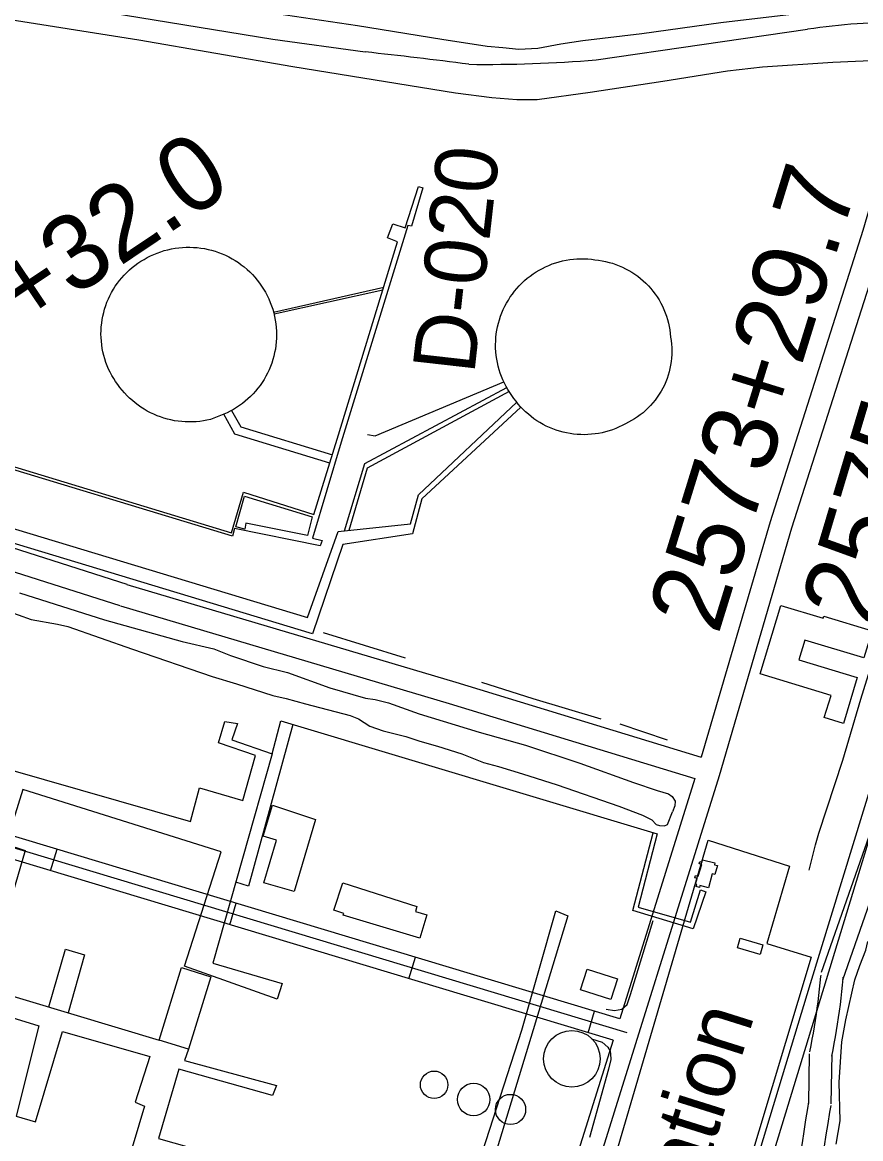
# Model space of a CAD drawing. Extents: x 3535183 to 3573198, y 534952 to 560562.
# Drawn here: x 3562347 to 3563467, y 541660 to 543150 of the extents above; entities that cross this region are included whole.
import ezdxf

# ---------------------------------------------------------------- set-up
doc = ezdxf.new("R2010")
doc.units = 0
for name, color, linetype in [('V-BLDG-OTLN', 7, 'Continuous'), ('V-DOMW-TANK', 7, 'Continuous'), ('V-LEVE-TOET', 7, 'Continuous'), ('V-RIVR-RANG-IDEN', 7, 'Continuous'), ('V-ROAD-CNTR', 7, 'Continuous'), ('V-SITE-OTLN', 7, 'Continuous'), ('V-SITE-OTLN-IDEN', 7, 'Continuous'), ('V-SURV-IDEN', 7, 'Continuous'), ('V-TOPO-SHOR', 7, 'Continuous'), ('V-UTIL-LINE', 7, 'Continuous')]:
    doc.layers.add(name, color=color, linetype=linetype)

msp = doc.modelspace()

# ---------------------------------------------------------------- linework, layer by layer
at = {"layer": 'V-BLDG-OTLN'}
for points in [[(3563427.4, 542251.8), (3563332.5, 542280.5), (3563360.1, 542371.9), (3563416.9, 542354.7), (3563417.8, 542357.6), (3563482.1, 542338.1), (3563471.2, 542301.7), (3563392.4, 542325.5), (3563384.4, 542299.3), (3563462.4, 542275.7), (3563443.9, 542214.4), (3563418.3, 542222.1)], [(3562738.4, 542086), (3562710, 541989.7), (3562669.6, 542001.6), (3562686.4, 542058.6), (3562668.7, 542063.8), (3562680.9, 542105.2)], [(3563255.4, 542032.1), (3563272.1, 542028.2), (3563271.5, 542025.7), (3563275.4, 542024.6), (3563272, 542012.7), (3563268.4, 542013.7), (3563263.7, 541995), (3563252.2, 541997.9), (3563251.6, 541995.1), (3563247.1, 541996.5), (3563247.8, 541999.3), (3563246.3, 541999.7), (3563248.4, 542007.1), (3563245.2, 542008), (3563246.4, 542011.2), (3563249.6, 542010.3), (3563254.5, 542026.1), (3563251.2, 542027), (3563252.1, 542030), (3563255.1, 542029.3)], [(3562887.3, 541958.8), (3562877.8, 541927.7), (3562775.5, 541958.3), (3562776.2, 541960.4), (3562763.1, 541964.8), (3562774.8, 542001.4), (3562874.1, 541969.7), (3562872.1, 541963.3)], [(3563305.9, 541927.6), (3563336.3, 541918.6), (3563332.4, 541905.6), (3563302.2, 541914.6)], [(3562598.8, 541876.1), (3562568.8, 541779.5), (3562529.6, 541791.6), (3562559.6, 541888.4)], [(3563101.6, 541886.3), (3563141.9, 541873.1), (3563133.2, 541845.8), (3563092.7, 541858.7)]]:
    msp.add_lwpolyline(points, close=True, dxfattribs=at)
at = {"layer": 'V-DOMW-TANK'}
for points in [[(3562458.5, 542696.4), (3562457, 542701), (3562455.7, 542705.6), (3562454.5, 542710.3), (3562453.6, 542715.1), (3562452.9, 542719.8), (3562452.4, 542724.6), (3562452, 542729.4), (3562451.9, 542734.2), (3562452, 542739.1), (3562452.3, 542743.9), (3562452.8, 542748.7), (3562453.5, 542753.4), (3562454.4, 542758.2), (3562455.5, 542762.9), (3562456.7, 542767.5), (3562458.2, 542772.1), (3562459.9, 542776.6), (3562461.8, 542781.1), (3562463.8, 542785.4), (3562466, 542789.7), (3562468.5, 542793.9), (3562471, 542797.9), (3562473.8, 542801.9), (3562476.7, 542805.7), (3562479.8, 542809.4), (3562483, 542813), (3562486.4, 542816.5), (3562489.9, 542819.8), (3562493.6, 542822.9), (3562497.3, 542825.9), (3562501.2, 542828.7), (3562505.3, 542831.4), (3562509.4, 542833.8), (3562513.6, 542836.2), (3562518, 542838.4), (3562522.5, 542840.4), (3562527.1, 542842.3), (3562531.7, 542844), (3562536.4, 542845.5), (3562541.2, 542846.7), (3562546, 542847.8), (3562550.8, 542848.7), (3562555.7, 542849.3), (3562560.6, 542849.8), (3562565.6, 542850.1), (3562570.5, 542850.1), (3562575.4, 542849.9), (3562580.4, 542849.6)], [(3562580.4, 542849.6), (3562585.2, 542849), (3562590.1, 542848.2), (3562595, 542847.2), (3562599.7, 542846), (3562604.5, 542844.7), (3562609.1, 542843.1), (3562613.7, 542841.3), (3562618.3, 542839.3), (3562622.7, 542837.2), (3562627, 542834.8), (3562631.3, 542832.3), (3562635.4, 542829.6), (3562639.4, 542826.7), (3562643.3, 542823.7), (3562647.1, 542820.5), (3562650.7, 542817.2), (3562654.2, 542813.7), (3562657.5, 542810), (3562660.7, 542806.2), (3562663.7, 542802.3), (3562666.5, 542798.3), (3562669.2, 542794.1), (3562671.7, 542789.9), (3562674, 542785.5), (3562676.1, 542781.1), (3562678, 542776.5), (3562679.8, 542771.9), (3562681.3, 542767.3), (3562682.7, 542762.5), (3562683.8, 542757.7), (3562684.8, 542752.9), (3562685.5, 542748), (3562686.1, 542743.1), (3562686.4, 542738.2), (3562686.5, 542733.3), (3562686.4, 542728.5), (3562686.1, 542723.7), (3562685.6, 542718.9), (3562684.9, 542714.1), (3562683.9, 542709.4), (3562682.8, 542704.7), (3562681.5, 542700), (3562680, 542695.4), (3562678.4, 542690.9), (3562676.5, 542686.5), (3562674.4, 542682.1), (3562672.2, 542677.8), (3562669.8, 542673.6), (3562667.2, 542669.6), (3562664.4, 542665.6), (3562661.5, 542661.7), (3562658.4, 542658), (3562655.2, 542654.4), (3562651.8, 542651), (3562648.3, 542647.7), (3562644.7, 542644.5), (3562640.9, 542641.5), (3562637, 542638.6), (3562633, 542636), (3562628.9, 542633.4), (3562624.6, 542631.1), (3562620.3, 542628.9), (3562615.9, 542627), (3562598.2, 542620.1), (3562593.4, 542619.1), (3562588.7, 542618.2), (3562583.9, 542617.6), (3562579, 542617.1), (3562574.2, 542616.8), (3562569.3, 542616.8), (3562564.5, 542616.9), (3562559.7, 542617.3), (3562554.8, 542617.8), (3562550, 542618.5), (3562545.3, 542619.5), (3562540.6, 542620.6), (3562535.9, 542622), (3562531.3, 542623.5), (3562526.8, 542625.2), (3562522.3, 542627.1), (3562517.9, 542629.2), (3562513.6, 542631.4), (3562509.4, 542633.9), (3562505.3, 542636.5), (3562501.4, 542639.2), (3562497.5, 542642.2), (3562493.8, 542645.3), (3562490.2, 542648.5), (3562486.7, 542651.9), (3562483.4, 542655.5), (3562480.2, 542659.1), (3562477.2, 542662.9), (3562474.3, 542666.7), (3562471.5, 542670.7), (3562468.9, 542674.7), (3562466.4, 542678.9), (3562464.2, 542683.1), (3562462.1, 542687.5), (3562460.2, 542691.9), (3562458.5, 542696.4)], [(3562998, 542656.1), (3562995.4, 542660.2), (3562993.1, 542664.3), (3562990.8, 542668.6), (3562988.8, 542673), (3562987, 542677.5), (3562985.3, 542682), (3562983.9, 542686.6), (3562982.6, 542691.3), (3562981.5, 542696), (3562980.6, 542700.7), (3562980, 542705.5), (3562979.5, 542710.3), (3562979.2, 542715.2), (3562979.1, 542720), (3562979.3, 542724.8), (3562979.6, 542729.6), (3562980.1, 542734.4), (3562980.9, 542739.2), (3562981.8, 542743.9), (3562982.9, 542748.6), (3562984.3, 542753.3), (3562985.8, 542757.9), (3562987.5, 542762.4), (3562989.4, 542766.8), (3562991.5, 542771.2), (3562993.7, 542775.5), (3562996.2, 542779.6), (3562998.8, 542783.7), (3563001.5, 542787.6), (3563004.5, 542791.5), (3563007.6, 542795.2), (3563010.8, 542798.7), (3563014.2, 542802.2), (3563017.8, 542805.5), (3563021.4, 542808.6), (3563025.2, 542811.6), (3563029.2, 542814.4), (3563033.2, 542817.1), (3563037.3, 542819.5), (3563041.6, 542821.8), (3563045.9, 542824), (3563050.3, 542825.9), (3563054.8, 542827.7), (3563059.4, 542829.2), (3563064, 542830.6), (3563068.7, 542831.8), (3563073.5, 542832.8), (3563078.2, 542833.5), (3563083, 542834.1), (3563087.8, 542834.5), (3563092.7, 542834.7), (3563097.5, 542834.7), (3563102.3, 542834.4), (3563107.1, 542834), (3563111.9, 542833.4)], [(3563111.9, 542833.4), (3563116.7, 542832.6), (3563121.4, 542831.9), (3563126.1, 542831), (3563130.7, 542829.9), (3563135.3, 542828.6), (3563139.8, 542827.1), (3563144.2, 542825.4), (3563148.6, 542823.5), (3563152.9, 542821.4), (3563157.1, 542819.2), (3563161.2, 542816.7), (3563165.2, 542814.1), (3563169.1, 542811.3), (3563172.8, 542808.4), (3563176.4, 542805.3), (3563179.9, 542802.1), (3563183.2, 542798.7), (3563186.4, 542795.1), (3563189.4, 542791.4), (3563192.3, 542787.6), (3563195, 542783.7), (3563197.5, 542779.7), (3563199.9, 542775.5), (3563202.1, 542771.3), (3563204.1, 542767), (3563205.9, 542762.6), (3563207.5, 542758.1), (3563208.9, 542753.5), (3563210.1, 542748.9), (3563211.1, 542744.3), (3563211.9, 542739.6), (3563212.5, 542734.9), (3563212.9, 542730.1), (3563213.7, 542725.5), (3563214.2, 542720.8), (3563214.5, 542716.1), (3563214.6, 542711.5), (3563214.6, 542706.8), (3563214.3, 542702.1), (3563213.7, 542697.4), (3563213, 542692.8), (3563212.1, 542688.2), (3563211, 542683.6), (3563209.7, 542679.1), (3563208.2, 542674.7), (3563206.5, 542670.3), (3563204.6, 542666), (3563202.5, 542661.8), (3563200.2, 542657.7), (3563197.8, 542653.7), (3563195.2, 542649.8), (3563192.4, 542646), (3563189.4, 542642.4), (3563186.3, 542638.9), (3563183, 542635.5), (3563179.6, 542632.3), (3563176.1, 542629.2), (3563172.4, 542626.3), (3563168.6, 542623.6), (3563164.7, 542621), (3563160.7, 542618.6), (3563156.5, 542616.4), (3563152.6, 542614.5), (3563148.4, 542612.2), (3563144.1, 542610.1), (3563139.7, 542608.2), (3563135.2, 542606.5), (3563130.7, 542605), (3563126.1, 542603.7), (3563121.4, 542602.5), (3563116.7, 542601.6), (3563112, 542600.9), (3563107.3, 542600.3), (3563102.5, 542600), (3563097.7, 542599.8), (3563092.9, 542599.9), (3563088.1, 542600.2), (3563083.4, 542600.6), (3563078.7, 542601.3), (3563073.9, 542602.1), (3563069.3, 542603.2), (3563064.7, 542604.4), (3563060.1, 542605.9), (3563055.6, 542607.5), (3563051.2, 542609.3), (3563046.8, 542611.4), (3563042.6, 542613.5), (3563038.4, 542615.9), (3563034.4, 542618.4), (3563030.4, 542621.1), (3563026.6, 542624), (3563022.9, 542627), (3563019.3, 542630.2), (3563015.9, 542633.5), (3563012.6, 542637), (3563009.5, 542640.6), (3563006.5, 542644.4), (3563003.6, 542648.2), (3563000.7, 542652.1), (3562998, 542656.1)]]:
    msp.add_lwpolyline(points, dxfattribs=at)
for centre, radius in [((3563081.1, 541766.6), 37.8), ((3562897, 541731.8), 18.4), ((3562949.8, 541712.2), 21.7), ((3562999.1, 541698.9), 20.2)]:
    msp.add_circle(centre, radius, dxfattribs=at)
at = {"layer": 'V-LEVE-TOET'}
msp.add_lwpolyline([(3563374.4, 543161), (3563280.1, 543149.6), (3563174.7, 543134.9), (3563095.8, 543125.7), (3563066.2, 543121), (3563035.4, 543115.5), (3563010.2, 543114.2), (3562989, 543116.1), (3562967.7, 543117.9), (3562907.2, 543127.4), (3562794.4, 543145.5), (3562674.5, 543163.6)], dxfattribs=at)
at = {"layer": 'V-ROAD-CNTR'}
for p, q in [((3562384.6, 542017.6), (3562393.2, 542046.3)), ((3562624, 541945.5), (3562632.6, 541974.3)), ((3562863.4, 541873.5), (3562872, 541902.2)), ((3563102.7, 541801.4), (3563111.4, 541830.1))]:
    msp.add_line(p, q, dxfattribs=at)
for points in [[(3562364.2, 543179.5), (3562681.6, 543128), (3562804.9, 543110.8)], [(3563551, 543149), (3563469.9, 542872.3), (3563345.8, 542483.6), (3563253.9, 542169.3)], [(3563580.9, 543140.1), (3563498.6, 542863.5), (3563374.5, 542474.8), (3563277.9, 542144.5), (3563109.1, 541604.2), (3563005.5, 541244.6)], [(3563113.6, 543100.4), (3563395.8, 543141.1)], [(3562486.8, 542399.8), (3562266.4, 542469.9), (3561935.4, 542567.8), (3561653.6, 542653.5), (3561243.7, 542788.4), (3561211.6, 542762.2), (3561208.6, 542724.7), (3561209.1, 542681.9), (3561219, 542659.5)], [(3563414.6, 541882), (3563493.9, 542108.1), (3563535.3, 542266.7), (3563581.7, 542416.5), (3563614.7, 542534.6)], [(3562477.7, 542371.2), (3562257.6, 542441.2), (3562153.2, 542472.1)], [(3562486.6, 542399.9), (3562925.8, 542269.6), (3563253.9, 542169.3)], [(3562478, 542371.1), (3562917.2, 542240.8), (3563245.2, 542140.6)], [(3563245.2, 542140.6), (3563145.1, 541820)], [(3563145.1, 541820), (3562118.9, 542128.9)], [(3563154.9, 541801.3), (3562114.6, 542114.6)], [(3563136.1, 541791.3), (3562110.3, 542100.2)], [(3563443, 541872), (3563515.7, 542079.6)], [(3563398.9, 541775.9), (3563400.6, 541784.3), (3563402.2, 541792.6), (3563403.7, 541800.9), (3563405.1, 541809.3), (3563406.5, 541817.6), (3563407.7, 541826), (3563408.9, 541834.3), (3563410, 541842.7), (3563411.1, 541851.1), (3563412, 541859.5), (3563412.9, 541867.9), (3563413.7, 541876.3), (3563413.9, 541878.3)], [(3563428.4, 541770.1), (3563430.1, 541778.6), (3563431.7, 541787.1), (3563433.2, 541795.7), (3563434.7, 541804.3), (3563436.1, 541813), (3563437.4, 541821.6), (3563438.6, 541830.2), (3563439.8, 541838.9), (3563440.8, 541847.6), (3563441.8, 541856.2), (3563442.7, 541864.9), (3563443.6, 541873.6), (3563443.7, 541875.7)], [(3563136.1, 541791.3), (3563080.3, 541612.9), (3562976.8, 541253.5)], [(3563397.5, 541707), (3563398.7, 541773.3)], [(3563427.5, 541706.5), (3563428.6, 541772.8)], [(3563382.4, 541608.6), (3563384.5, 541623.8), (3563386.7, 541639.1), (3563389, 541654.4), (3563391.3, 541669.7), (3563393.7, 541685), (3563396.2, 541700.3), (3563397.8, 541709.2)], [(3563412.1, 541604.5), (3563414.2, 541619.7), (3563416.4, 541634.8), (3563418.6, 541650), (3563420.9, 541665.1), (3563423.4, 541680.2), (3563425.8, 541695.3), (3563427.3, 541704.2)]]:
    msp.add_lwpolyline(points, dxfattribs=at)
for centre, radius, start, end in [((3563518.7, 542328.8), 821.5, 89.2963, 98.6004), ((3562148.1, 536981.3), 6164.6, 82.58832, 83.88403), ((3562969.2, 544782.2), 1688, 269.1236, 274.9081)]:
    msp.add_arc(centre, radius, start, end, dxfattribs=at)
at = {"layer": 'V-SITE-OTLN'}
for p, q in [((3562207.1, 543173.4), (3562502.6, 543127)), ((3562502.6, 543127), (3562708.1, 543091.2)), ((3562708.1, 543091.2), (3562925.4, 543056.4)), ((3563288.8, 543085.4), (3563335.8, 543091.1)), ((3563335.8, 543091.1), (3563429.6, 543097.3)), ((3563429.6, 543097.3), (3563517.1, 543100.9)), ((3563202.4, 543072), (3563288.8, 543085.4)), ((3563105.7, 543057.1), (3563202.4, 543072)), ((3562925.4, 543056.4), (3562974.1, 543049.8)), ((3562974.1, 543049.8), (3563007.6, 543047.4)), ((3563007.6, 543047.4), (3563034.7, 543047.4)), ((3563034.7, 543047.4), (3563105.7, 543057.1))]:
    msp.add_line(p, q, dxfattribs=at)
msp.add_lwpolyline([(3563027.8, 541258), (3563263.1, 542058.4), (3563371.7, 542023.6), (3563341.5, 541920.3), (3563400.8, 541902.3), (3563192.2, 541209.8)], close=True, dxfattribs=at)
at = {"layer": 'V-TOPO-SHOR'}
for p, q in [((3562748.9, 542335.8), (3562858.5, 542301.7)), ((3563145.2, 542213.7), (3563208.3, 542192.2))]:
    msp.add_line(p, q, dxfattribs=at)
for points in [[(3562343.1, 542388.5), (3562456.7, 542352.4), (3562560.4, 542323.8), (3562602.7, 542313.7), (3562624.9, 542304.8), (3562668.5, 542290.3), (3562700.9, 542282.3), (3562757.5, 542261.9), (3562805.3, 542247.9), (3562818.1, 542246.4), (3562836.2, 542241.9), (3562877.1, 542227.2), (3562957.3, 542202.6), (3563019.2, 542185.2), (3563091.8, 542161.2), (3563163.5, 542135.3), (3563194.8, 542124.7), (3563210, 542120.3), (3563214.9, 542116.8), (3563219, 542110.5), (3563218.7, 542104.4), (3563215.4, 542096.1)], [(3562323.7, 542365.4), (3562358.7, 542353.2), (3562393.7, 542346.9), (3562407.8, 542343.6), (3562493.9, 542313.6), (3562600.4, 542276.8), (3562632.8, 542267.2), (3562681.6, 542251.6), (3562699.1, 542247.7), (3562725, 542240.5), (3562784.6, 542225.1), (3562796, 542220.5), (3562803.6, 542215.4), (3562811.1, 542210.6), (3562828.9, 542204.6), (3562859.4, 542196.8), (3562877.7, 542190.5), (3562901.7, 542183.9), (3562934.1, 542173.8), (3562962.8, 542162.1), (3562982.9, 542156.9), (3563015, 542147), (3563061.5, 542132.5), (3563143.7, 542103.9), (3563175.5, 542091.9), (3563188, 542085.5), (3563193.7, 542079.3), (3563198.2, 542078.2), (3563204.7, 542077.4), (3563208.7, 542079.4), (3563215.4, 542096.1)], [(3563397.9, 542018.4), (3563406.4, 542052), (3563410.8, 542067.9), (3563443, 542165.2), (3563466.9, 542246.6), (3563485.2, 542305.5)], [(3562960.3, 542269.4), (3563028.9, 542247.8), (3563119.8, 542220.3)], [(3563126.7, 541833), (3563138, 541831), (3563147.7, 541832.7), (3563154.8, 541839.2), (3563159.2, 541852.2), (3563189.6, 541951.2)], [(3563434.3, 541652.8), (3563439.4, 541683.6), (3563438, 541735.2), (3563441.6, 541789.4), (3563447.2, 541818.7), (3563458.9, 541871.9), (3563465.7, 541891.2), (3563473.6, 541911.8), (3563476.4, 541923)], [(3563107.3, 541793.4), (3563121.4, 541788.7), (3563128.9, 541782.3), (3563132, 541776.8), (3563132.5, 541773.1), (3563133.1, 541765.5), (3563129.8, 541752.7), (3563104.7, 541661.5)]]:
    msp.add_lwpolyline(points, dxfattribs=at)
at = {"layer": 'V-UTIL-LINE'}
for p, q in [((3562682.4, 542763.5), (3562829.6, 542796.9)), ((3562828.4, 542792.9), (3562683.2, 542760.5)), ((3563162.3, 541964.4), (3563189.7, 542068.4))]:
    msp.add_line(p, q, dxfattribs=at)
for points in [[(3562600.6, 541325.2), (3563183, 541152.3), (3563400, 541867.3), (3563555.5, 542372.9), (3563714.9, 542897.4), (3563765, 543065.4), (3563829.1, 543275.6), (3563757.2, 543365.8), (3563775.5, 543379.1), (3563851.7, 543278.9), (3563779.3, 543058.9), (3563610.5, 542507.4), (3563502.9, 542150), (3563833.4, 542045.4), (3564045.4, 541982.5)], [(3562882, 542929.6), (3562866.9, 542878.4), (3562862, 542878.9), (3562772.9, 542589.7), (3562734.6, 542461.7), (3562747.2, 542458.4), (3562744.9, 542451.2), (3562630.2, 542474.4), (3562627.4, 542464.5), (3562263.1, 542574.9), (3562264.1, 542578.9), (3562626.1, 542468.6), (3562642.1, 542522.9), (3562736.4, 542493.3), (3562767.5, 542593.9), (3562848.1, 542857.5), (3562834.7, 542862.6), (3562841.7, 542881.4), (3562858.3, 542875.8)], [(3562858.3, 542875.8), (3562876.2, 542931), (3562882, 542929.6)], [(3560372.3, 541690.8), (3560698.4, 541935.3), (3560422.4, 542064.4), (3560428.9, 542080.5), (3560704, 541949.7), (3560873.9, 542038.5), (3560853.9, 542092.9), (3561003.7, 542576.1), (3561122.2, 542535.7), (3561205.3, 542816), (3562727.8, 542355.6), (3562769, 542470.4), (3562865.6, 542480.9), (3562876, 542519.5), (3563007.4, 542643.1)], [(3563012.9, 542636.7), (3562880.5, 542514), (3562868.1, 542467.3), (3562775.1, 542453.2), (3562734.7, 542333.8), (3562010.7, 542552.7), (3561508.6, 542705.5), (3561417.1, 542401.9), (3561327.5, 542107.3), (3561444.3, 542074.2), (3561548.1, 542419.1)], [(3562808.1, 542600.1), (3562818, 542598.1), (3562990.1, 542670.2)], [(3562777.2, 542471.3), (3562804.5, 542561.3), (3562994, 542662.6)], [(3562997.2, 542657.3), (3562807.6, 542555), (3562783, 542472)], [(3562757.5, 542561.6), (3562630.9, 542600.7), (3562615.9, 542627)], [(3562626.2, 542632), (3562638.7, 542610.4), (3562761.1, 542573)], [(3562643.7, 542517.6), (3562734, 542490.2), (3562727.8, 542465.1), (3562645.5, 542481.5), (3562644, 542473.8), (3562631.9, 542476.7), (3562643.7, 542517.6)], [(3562327.9, 542153.2), (3562571.3, 542083.2), (3562583.7, 542128.2), (3562641.2, 542111.2), (3562658.2, 542171.3), (3562608.8, 542188.2), (3562617.3, 542217), (3562634.4, 542214.1), (3562626.9, 542192.5), (3562680.8, 542173.8), (3562692.2, 542217.8), (3563195.2, 542066.8), (3563169.5, 541968.8), (3563239.6, 541949), (3563252.8, 541992.1), (3563260, 541989.3), (3563243.1, 541939.9), (3563162.3, 541964.4)], [(3562708.4, 542212.9), (3562649.2, 541997.1), (3562632, 542002.3)], [(3562680.8, 542173.8), (3562601.3, 541894.3), (3562693.8, 541867), (3562687.2, 541846.3), (3562563.4, 541890.3), (3562612.3, 542043), (3562347.4, 542125.9), (3562324.7, 542053.2), (3562350.8, 542044.7), (3562296.9, 541861.4), (3562529.6, 541791.6)], [(3564040.9, 541964.7), (3563499, 542128.9), (3563361.4, 541678), (3563218, 541209.2), (3563758.8, 541042.3)], [(3562568.8, 541779.5), (3562563.5, 541764.1), (3562686.6, 541730.9), (3562681, 541717.4), (3562556.1, 541752.5), (3562528.7, 541660), (3562747.9, 541598.4), (3562745.1, 541588.5), (3562820.5, 541564.1), (3562814.9, 541547), (3562511.3, 541636.7), (3562480, 541519.9), (3562885.2, 541405.4), (3563014, 541805), (3563059.5, 541964), (3563075.6, 541957.5), (3562899.2, 541378.2), (3562642.1, 541454.4)], [(3562382.4, 541835.8), (3562404.6, 541912.9), (3562429.8, 541905.3), (3562408.1, 541828.1)], [(3562291.8, 541834.1), (3562369, 541810.5), (3562338.5, 541690.1), (3562364.6, 541682.5), (3562400.5, 541802.9), (3562517.3, 541769.8), (3562497.5, 541708.7), (3562510.1, 541703.1), (3562461.9, 541542.4), (3562447.5, 541545.3), (3562444.6, 541530), (3562404.2, 541544), (3562406.1, 541551.2), (3562377.4, 541558.8), (3562374.6, 541552.5), (3562286.6, 541580.8), (3562289.4, 541588), (3562258.8, 541598.3), (3562256, 541586.6), (3562199.4, 541604.5), (3562258.3, 541824.6), (3562284.3, 541818)]]:
    msp.add_lwpolyline(points, dxfattribs=at)

# ---------------------------------------------------------------- texts
at = {"layer": 'V-RIVR-RANG-IDEN'}
msp.add_text('D-020', height=83, rotation=83.5543, dxfattribs=at).set_placement((3562950.5, 542679.4))
at = {"layer": 'V-SITE-OTLN-IDEN'}
msp.add_text('Substation', height=83, rotation=72.511, dxfattribs=at).set_placement((3563167.6, 541323.6))
at = {"layer": 'V-SURV-IDEN'}
for s, rotation, p in [('2567+32.0', 33.8486, (3562102.7, 542573.2)), ('2573+29.7', 72.8051, (3563276.5, 542331.4)), ('2575+86.0', 73.3255, (3563481.1, 542342.2))]:
    msp.add_text(s, height=100, rotation=rotation, dxfattribs=at).set_placement(p)

doc.saveas('drawing.dxf')
